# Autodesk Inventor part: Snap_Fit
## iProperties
Created: 2008-12
Part Number: Snap_Fit
Document SubType Name: Modeling
Designer: EAO
Density: 1 g/cm^3
Author: EAO
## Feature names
1. Extrusion1
2. Fillet1
3. Fillet2
4. Shell1
5. Extrusion2
6. Extrusion3
7. Fillet3
8. Extrusion4
9. Extrusion6
10. Extrusion7
11. Extrusion8
12. Fillet5
13. Extrusion10
14. Extrusion11
15. Extrusion12
16. Extrusion13
17. Extrusion14
18. Chamfer1
